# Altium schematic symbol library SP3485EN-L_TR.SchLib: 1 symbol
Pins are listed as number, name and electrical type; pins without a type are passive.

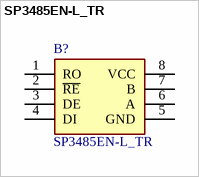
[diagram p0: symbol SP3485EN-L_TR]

## SP3485EN-L_TR
designator B?
RS-485 Interface IC 3.3V LoPwr Half-Dup RS485w/10Mbps Data; Manufacturer_Name: MaxLinear, Inc.; Manufacturer_Part_Number: SP3485EN-L/TR; Geometry.Height: 1.75mm
footprint SOIC127P600X175-8N
pins: 1 RO, 2 ~{RE}, 3 DE, 4 DI, 5 GND, 6 A, 7 B, 8 VCC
